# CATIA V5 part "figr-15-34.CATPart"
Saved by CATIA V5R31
Part number: Part1
Bounding box of the stored display mesh (mm): x -40.264 to 42.014, y -25.445 to 25.445, z -51 to 0.75
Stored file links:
  D:\PROJECTS\Project 2021\US EDITION\CATIA V5 6R 2021\Resources\Part Files\c15_catia_v5_6r2021_prt\figr-15-34.CATPart
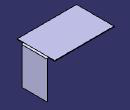
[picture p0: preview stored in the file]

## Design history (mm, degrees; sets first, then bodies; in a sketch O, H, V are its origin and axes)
SheetMetalParameters1: Thickness 0.75, BendRadius 1, KFactor 0.356492 {= log(min(100,max(20*SheetMetalParameters1.BendRadius,SheetMetalParameters1.Thickness)/SheetMetalParameters1.Thickness))/log(100)/2}, ReliefRadialLength 1, ReliefAxialLength 2, MinimumBendRadius 0
Body1 (main body)
  Sketch1 on xy-plane, origin (0, 0, 0), H (1, 0, 0), V (0, 1, 0)
    line L1 (-40.2643, 25.445) -> (40.2643, 25.445)
    line L2 (40.2643, 25.445) -> (40.2643, -25.445)
    line L3 (40.2643, -25.445) -> (-40.2643, -25.445)
    line L4 (-40.2643, -25.445) -> (-40.2643, 25.445)
    horizontal: L1 H, L3 H
    vertical: L2 V, L4 V
    symmetry: L1 L3 H, L4 L2 V
  Wall1: Thickness 0.75, Profile Sketch1
  Plane1: type Offset, RefPlane zx-plane, Offset 17
  Plane2: type Offset, RefPlane zx-plane, Offset 17, reversed
  Flange1: Angle 90, Length 50, Radius 1, KFacteur 0.356492 {= log(min(100,max(20*Flange1.Radius,SheetMetalParameters1.Thickness)/SheetMetalParameters1.Thickness))/log(100)/2}, Guide edge [face of Wall1 | face of Wall1], Limit1 Plane1, Limit2 Plane2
